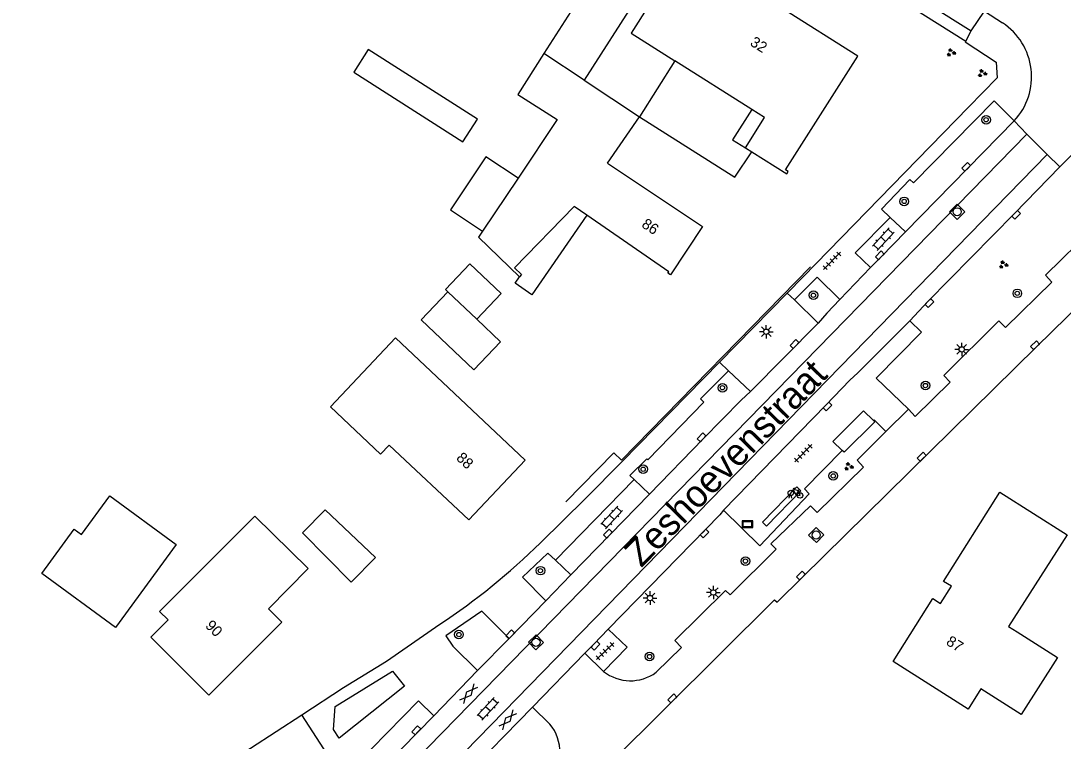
# Model space of a CAD drawing. Extents: x 136000 to 141000, y 400494 to 402006.
# Drawn here: x 137911.7 to 138008.3, y 401818.6 to 401885.4 of the extents above; entities that cross this region are included whole.
import ezdxf

# ---------------------------------------------------------------- set-up
doc = ezdxf.new("R2010")
doc.units = 0
for name, color, linetype in [('gg-afsc-erfafscheiding', 7, 'Continuous'), ('gg-afsc-haag', 7, 'Continuous'), ('gg-afsc-hekwerk', 7, 'Continuous'), ('gg-afsc-muur', 7, 'Continuous'), ('gg-anno-huisnummerreeks BGT', 7, 'Continuous'), ('gg-anno-openbare ruimte label', 7, 'Continuous'), ('gg-bbg-abri', 7, 'Continuous'), ('gg-bbg-bijgebouw', 7, 'Continuous'), ('gg-bbg-gedigitaliseerde bebouwing', 7, 'Continuous'), ('gg-bbg-gedigitaliseerde bijgebouw', 7, 'Continuous'), ('gg-bbg-hoofdgebouw', 7, 'Continuous'), ('gg-bbg-luifel en loopbrug', 7, 'Continuous'), ('gg-bbg-tussenscheiding', 7, 'Continuous'), ('gg-knt-verharding', 7, 'Continuous'), ('gg-knt-verharding nz', 7, 'Continuous'), ('gt-grn-weggrens', 7, 'Continuous'), ('gt-symb-boom', 7, 'Continuous'), ('gt-symb-fietsenrek', 7, 'Continuous'), ('gt-symb-gesloten verharding', 7, 'Continuous'), ('gt-symb-groenvak', 7, 'Continuous'), ('gt-symb-informatiebord', 7, 'Continuous'), ('gt-symb-klinker verharding', 7, 'Continuous'), ('gt-symb-kolk', 7, 'Continuous'), ('gt-symb-lichtmast', 7, 'Continuous'), ('gt-symb-rioolschacht', 7, 'Continuous'), ('gt-symb-tegel verharding', 7, 'Continuous')]:
    doc.layers.add(name, color=color, linetype=linetype)

# ---------------------------------------------------------------- blocks, each defined once
blk = doc.blocks.new('gt0-BOOM')
at = {"layer": 'gt-symb-boom'}
for radius in [0.4, 0.2]:
    blk.add_circle((0, 0), radius, dxfattribs=at)
blk = doc.blocks.new('gt0-GRVAK')
at = {"layer": 'gt-symb-groenvak'}
for p, q in [((-0.11, 0.189), (-0.228, 0.24)), ((-0.182, 0.153), (0.088, 0.153)), ((-0.091, 0.211), (-0.156, 0.322)), ((-0.047, 0.214), (-0.047, 0.393)), ((-0.004, 0.211), (0.061, 0.322)), ((0.015, 0.189), (0.133, 0.24)), ((0.262, -0.052), (0.197, 0.059)), ((0.305, -0.049), (0.305, 0.13)), ((0.349, -0.052), (0.414, 0.059)), ((-0.245, -0.228), (-0.363, -0.177)), ((-0.318, -0.264), (-0.047, -0.264)), ((-0.226, -0.206), (-0.291, -0.095)), ((-0.183, -0.203), (-0.183, -0.024)), ((-0.139, -0.206), (-0.074, -0.095)), ((-0.12, -0.228), (-0.002, -0.177)), ((0.243, -0.074), (0.125, -0.023)), ((0.17, -0.11), (0.441, -0.11)), ((0.368, -0.074), (0.486, -0.023))]:
    blk.add_line(p, q, dxfattribs=at)
blk = doc.blocks.new('gt0-TEG1')
at = {"layer": 'gt-symb-tegel verharding'}
for p, q in [((-1.125, 0), (1.125, 0)), ((-0.9, -0.25), (-0.9, 0.25)), ((-0.45, -0.25), (-0.45, 0.25)), ((0, -0.25), (0, 0.25)), ((0.45, -0.25), (0.45, 0.25)), ((0.9, -0.25), (0.9, 0.25))]:
    blk.add_line(p, q, dxfattribs=at)
blk = doc.blocks.new('gt0-KOLK')
at = {"layer": 'gt-symb-kolk'}
blk.add_lwpolyline([(0, 0), (0.375, 0), (0.375, 0.4), (-0.375, 0.4), (-0.375, 0), (0, 0)], dxfattribs=at)
blk = doc.blocks.new('gt0-KL1')
at = {"layer": 'gt-symb-klinker verharding'}
for p, q in [((-1.15, 0.3), (1.15, 0.3)), ((-1, -0.3), (-1, 0.3)), ((-0.5, 0.3), (-0.5, 0.45)), ((0, -0.3), (0, 0.3)), ((0.5, 0.3), (0.5, 0.45)), ((1, -0.3), (1, 0.3)), ((-1.15, -0.3), (1.15, -0.3)), ((-0.5, -0.45), (-0.5, -0.3)), ((0.5, -0.45), (0.5, -0.3))]:
    blk.add_line(p, q, dxfattribs=at)
blk = doc.blocks.new('gt0-LMAST')
at = {"layer": 'gt-symb-lichtmast'}
for p, q in [((-0.182, 0.173), (-0.447, 0.438)), ((-0.005, 0.246), (-0.005, 0.621)), ((0.172, 0.173), (0.437, 0.438)), ((-0.255, -0.004), (-0.63, -0.004)), ((-0.182, -0.181), (-0.447, -0.446)), ((-0.005, -0.254), (-0.005, -0.629)), ((0.437, -0.446), (0.172, -0.181)), ((0.245, -0.004), (0.62, -0.004))]:
    blk.add_line(p, q, dxfattribs=at)
blk.add_circle((-0.005, -0.004), 0.25, dxfattribs=at)
blk = doc.blocks.new('gt0-RS')
at = {"layer": 'gt-symb-rioolschacht'}
blk.add_lwpolyline([(-0.5, -0.5), (0.5, -0.5), (0.5, 0.5), (-0.5, 0.5)], close=True, dxfattribs=at)
blk.add_circle((0, 0), 0.375, dxfattribs=at)
blk = doc.blocks.new('gt0-IBORD')
at = {"layer": 'gt-symb-informatiebord'}
blk.add_lwpolyline([(-0.5, 0.295), (-0.5, -0.295), (0.5, -0.295), (0.5, 0.295), (-0.5, 0.295)], dxfattribs=at)
blk.add_lwpolyline([(-0.417, -0.212), (0.417, -0.212), (0.417, 0.212), (-0.417, 0.212)], close=True, dxfattribs=at)
blk = doc.blocks.new('gt0-FREK')
at = {"layer": 'gt-symb-fietsenrek'}
for p, q in [((0.259, 0.762), (0.294, 0.823)), ((0.54, 0.335), (0.259, 0.762)), ((0.294, 0.823), (0.767, 0.714)), ((0.767, 0.714), (0.54, 0.335)), ((0.757, 0.841), (0.866, 0.816)), ((0.767, 0.714), (0.84, 0.822)), ((0.895, 0.252), (0.767, 0.714))]:
    blk.add_line(p, q, dxfattribs=at)
for points in [[(-0.124, 0), (-0.047, 0.312), (0.053, 0.312), (0.12, 0)], [(0.036, 0.476), (0.228, 0.708), (0.259, 0.762)], [(0.294, 0.823), (0.36, 0.937), (0.452, 0.935)], [(0.54, 0.335), (0.555, 0.305), (0.895, 0.252)]]:
    blk.add_lwpolyline(points, dxfattribs=at)
for centre in [(0.036, 0.476), (0.895, 0.252)]:
    blk.add_circle(centre, 0.252, dxfattribs=at)
blk = doc.blocks.new('gt0-GESVH1')
at = {"layer": 'gt-symb-gesloten verharding'}
for p, q in [((-0.992, -0.261), (0.008, 0.239)), ((0.008, -0.261), (-0.992, 0.239)), ((0.008, 0.239), (1.008, -0.261)), ((1.008, 0.239), (0.008, -0.261))]:
    blk.add_line(p, q, dxfattribs=at)

msp = doc.modelspace()

# ---------------------------------------------------------------- linework, layer by layer
at = {"layer": 'gg-afsc-erfafscheiding'}
msp.add_line((137966.665, 401845.333), (137962.24, 401840.784), dxfattribs=at)
at = {"layer": 'gg-afsc-haag'}
msp.add_line((137916.005, 401806.962), (137937.768, 401821.037), dxfattribs=at)
at = {"layer": 'gg-afsc-hekwerk'}
msp.add_lwpolyline([(137984.892, 401862.572), (137967.38, 401844.635), (137966.665, 401845.333)], dxfattribs=at)
at = {"layer": 'gg-afsc-muur'}
msp.add_lwpolyline([(137969.048, 401876.493), (137977.887, 401870.892), (137979.45, 401873.22)], dxfattribs=at)
at = {"layer": 'gg-bbg-abri'}
for points in [[(137990.721, 401848.334), (137989.795, 401849.216), (137986.958, 401846.389), (137987.834, 401845.555)], [(137990.721, 401848.334), (137990.855, 401848.206), (137988.018, 401845.379), (137987.834, 401845.555)]]:
    msp.add_lwpolyline(points, dxfattribs=at)
at = {"layer": 'gg-bbg-bijgebouw'}
msp.add_line((137942.35, 401833.35), (137944.6, 401835.64), dxfattribs=at)
at = {"layer": 'gg-bbg-gedigitaliseerde bebouwing'}
for p, q in [((137969.96, 401886.87), (137968.282, 401884.244)), ((137968.282, 401884.244), (137972.322, 401881.679)), ((137963.923, 401879.878), (137960.191, 401882.343)), ((137979.46, 401877.172), (137972.322, 401881.679)), ((137963.923, 401879.878), (137969.048, 401876.493)), ((137957.799, 401870.791), (137954.52, 401865.877))]:
    msp.add_line(p, q, dxfattribs=at)
for points in [[(137960.191, 401882.343), (137957.767, 401878.552), (137961.424, 401876.221), (137957.799, 401870.791)], [(137978.861, 401873.592), (137980.647, 401876.422), (137979.46, 401877.172)], [(137954.52, 401865.877), (137954.15, 401865.324), (137957.93, 401861.66)], [(137958.47, 401844.66), (137946.444, 401855.982), (137940.412, 401849.581)], [(138002.431, 401841.67), (138008.667, 401837.735), (138003.255, 401829.217), (138004.036, 401828.72)], [(137938.34, 401834.61), (137933.399, 401839.446), (137924.592, 401830.612), (137925.374, 401829.832), (137923.78, 401828.234), (137929.16, 401822.87)], [(138004.036, 401828.72), (138007.775, 401826.345), (138004.424, 401821.07), (138000.685, 401823.445)], [(138000.685, 401823.445), (137999.495, 401821.572), (137992.54, 401825.978)]]:
    msp.add_lwpolyline(points, dxfattribs=at)
at = {"layer": 'gg-bbg-gedigitaliseerde bijgebouw'}
for p, q in [((137965.08, 401889.99), (137960.191, 401882.343)), ((137968.848, 401887.581), (137963.923, 401879.878)), ((137953.967, 401857.71), (137956.167, 401855.619))]:
    msp.add_line(p, q, dxfattribs=at)
for points in [[(137951.286, 401860.26), (137951.069, 401860.467), (137953.343, 401862.858), (137956.241, 401860.102), (137953.967, 401857.71)], [(137956.167, 401855.619), (137953.692, 401853.015), (137948.811, 401857.657), (137951.286, 401860.26)], [(137926.129, 401836.838), (137920.498, 401829.133), (137913.664, 401834.127), (137916.676, 401838.248), (137917.36, 401837.748), (137919.98, 401841.332), (137926.129, 401836.838)], [(137942.35, 401833.35), (137937.824, 401837.911), (137939.935, 401840.053), (137944.6, 401835.64)]]:
    msp.add_lwpolyline(points, dxfattribs=at)
at = {"layer": 'gg-bbg-hoofdgebouw'}
for p, q in [((137966.073, 401872.186), (137969.048, 401876.493)), ((137978.861, 401873.592), (137979.45, 401873.22)), ((137979.45, 401873.22), (137982.69, 401871.2))]:
    msp.add_line(p, q, dxfattribs=at)
for points in [[(137982.69, 401871.2), (137982.83, 401871.42), (137982.57, 401871.58), (137989.27, 401882.11), (137975.39, 401890.92), (137975.23, 401890.65)], [(137966.073, 401872.186), (137974.9, 401866.3), (137971.91, 401861.82), (137971.69, 401861.99), (137971.77, 401862.1), (137964.175, 401867.351)], [(137964.175, 401867.351), (137962.99, 401868.17), (137957.48, 401862.47), (137958.12, 401861.85), (137957.93, 401861.66)], [(137940.412, 401849.581), (137945.07, 401845.2), (137945.87, 401846.05), (137953.25, 401839.12), (137958.47, 401844.66)], [(137996.95, 401831.369), (137997.96, 401832.96), (137997.23, 401833.4), (138002.431, 401841.67)], [(137938.34, 401834.61), (137934.68, 401830.85), (137935.9, 401829.63), (137929.16, 401822.87)], [(137992.54, 401825.978), (137996.24, 401831.82), (137996.95, 401831.369)]]:
    msp.add_lwpolyline(points, dxfattribs=at)
at = {"layer": 'gg-bbg-luifel en loopbrug'}
msp.add_line((137972.322, 401881.679), (137969.048, 401876.493), dxfattribs=at)
for points in [[(137942.573, 401880.627), (137952.683, 401874.164), (137954.03, 401876.271), (137943.919, 401882.734), (137942.573, 401880.627)], [(137979.46, 401877.172), (137977.673, 401874.342), (137978.861, 401873.592)], [(137957.799, 401870.791), (137954.819, 401872.78), (137951.539, 401867.865), (137954.52, 401865.877)], [(137964.175, 401867.351), (137959.083, 401859.986), (137957.52, 401861.067), (137957.93, 401861.66)]]:
    msp.add_lwpolyline(points, dxfattribs=at)
at = {"layer": 'gg-bbg-tussenscheiding'}
msp.add_line((137951.286, 401860.26), (137953.967, 401857.71), dxfattribs=at)
at = {"layer": 'gg-knt-verharding'}
for p, q in [((137999.783, 401884.462), (138001.016, 401886.274)), ((138001.016, 401886.274), (138002.691, 401885.196)), ((137993.703, 401865.811), (138003.775, 401876.119)), ((138003.775, 401876.119), (138004.946, 401874.871)), ((138004.946, 401874.871), (138006.822, 401873.001)), ((138008.003, 401871.833), (138010.68, 401874.563)), ((138006.822, 401873.001), (137934.076, 401798.339)), ((138006.822, 401873.001), (138008.003, 401871.833)), ((137993.703, 401865.811), (137992.291, 401867.156)), ((137990.467, 401862.498), (137987.619, 401859.546)), ((137976.468, 401853.726), (137982.747, 401860.138)), ((137985.617, 401857.363), (137983.42, 401859.501)), ((137979.344, 401851.006), (137985.617, 401857.363)), ((137977.295, 401852.944), (137979.344, 401851.006)), ((137991.861, 401847.318), (137993.98, 401849.373)), ((137961.258, 401835.373), (137968.562, 401842.868)), ((137969.975, 401841.49), (137968.562, 401842.868)), ((137962.685, 401834.01), (137969.975, 401841.49)), ((137962.685, 401834.01), (137961.258, 401835.373)), ((137960.381, 401831.615), (137962.685, 401834.01)), ((137956.985, 401828.13), (137960.381, 401831.615)), ((137954.059, 401825.141), (137956.985, 401828.13)), ((137959.138, 401821.751), (137963.991, 401826.745)), ((137963.991, 401826.745), (137965.72, 401825.067)), ((137949.996, 401820.95), (137954.059, 401825.141)), ((137948.592, 401822.35), (137939.895, 401813.463)), ((137949.996, 401820.95), (137948.592, 401822.35)), ((137940.145, 401817.354), (137937.768, 401821.037)), ((137960.747, 401820.185), (137959.138, 401821.751)), ((137941.293, 401812.071), (137949.996, 401820.95))]:
    msp.add_line(p, q, dxfattribs=at)
for points in [[(137880.886, 401957.924), (137937.788, 401922.146), (137999.278, 401883.51)], [(137989.798, 401893.33), (137988.63, 401891.471), (137999.783, 401884.462)], [(137999.278, 401883.51), (137999.225, 401883.426), (138002.104, 401881.541), (138002.204, 401880.088)], [(137982.747, 401860.138), (137984.229, 401861.651), (137999.534, 401877.377), (138002.204, 401880.088)], [(138003.775, 401876.119), (138001.905, 401877.968), (137994.428, 401870.364), (137994.114, 401870.661), (137991.46, 401867.921), (137992.291, 401867.156)], [(138004.946, 401874.871), (137943.022, 401811.44), (137931.758, 401800.418), (137930.613, 401801.602)], [(137994.085, 401857.576), (137995.78, 401859.347), (138003.81, 401867.529), (138008.003, 401871.833)], [(137993.98, 401849.373), (137994.602, 401848.707), (137997.831, 401851.865), (137997.236, 401852.507), (138002.36, 401857.569), (138002.966, 401856.941), (138007.261, 401861.154), (138006.667, 401861.81), (138011.086, 401866.119), (138011.726, 401865.513), (138015.663, 401869.388), (138015.084, 401869.969), (138015.852, 401870.833)], [(137932.851, 401783.862), (137933.76, 401784.767), (137934.015, 401784.527), (137961.351, 401811.623), (137981.568, 401831.695), (137981.799, 401831.48), (137984.14, 401833.81), (138005.833, 401855.156), (138020.002, 401869.043)], [(137992.291, 401867.156), (137989.034, 401863.876), (137990.467, 401862.498)], [(137990.467, 401862.498), (137991.455, 401863.495), (137993.703, 401865.811)], [(137983.42, 401859.501), (137985.521, 401861.612), (137987.619, 401859.546)], [(137987.619, 401859.546), (137986.408, 401858.291), (137985.617, 401857.363)], [(137976.842, 401840.025), (137986.329, 401849.759), (137988.555, 401852.065), (137989.291, 401852.732), (137994.085, 401857.576)], [(137993.98, 401849.373), (137990.977, 401852.249), (137995.168, 401856.509), (137994.085, 401857.576)], [(137959.866, 401836.993), (137964.058, 401841.093), (137967.461, 401844.528), (137976.468, 401853.726)], [(137968.562, 401842.868), (137968.171, 401843.234), (137969.718, 401844.773), (137969.834, 401844.69), (137975.016, 401850.014), (137974.694, 401850.328), (137977.295, 401852.944)], [(137969.975, 401841.49), (137974.952, 401846.62), (137978.485, 401850.211), (137979.344, 401851.006)], [(137991.861, 401847.318), (137990.781, 401848.399), (137990.721, 401848.334)], [(137970.582, 401824.98), (137972.951, 401827.279), (137972.316, 401827.938), (137977.01, 401832.577), (137977.454, 401832.177), (137981.701, 401836.383), (137981.215, 401836.893), (137984.897, 401840.417), (137985.524, 401839.797), (137989.8, 401844.009), (137989.227, 401844.658), (137991.861, 401847.318)], [(137987.834, 401845.555), (137984.348, 401841.989), (137984.786, 401841.529), (137980.208, 401836.692), (137976.842, 401840.025)], [(137976.842, 401840.025), (137976.491, 401839.573), (137966.137, 401828.969)], [(137961.258, 401835.373), (137960.575, 401836.017), (137958.216, 401833.788), (137960.381, 401831.615)], [(137956.985, 401828.13), (137954.449, 401830.653), (137951.115, 401828.353), (137951.744, 401827.402), (137954.059, 401825.141)], [(137937.768, 401821.037), (137941.643, 401823.562), (137945.627, 401826.006), (137950.54, 401829.437)], [(137966.137, 401828.969), (137964.834, 401827.596), (137963.991, 401826.745)], [(137965.72, 401825.067), (137967.911, 401827.312), (137966.137, 401828.969)], [(137947.285, 401823.701), (137941.221, 401818.875), (137940.705, 401819.664), (137940.869, 401821.819), (137946.168, 401825.092), (137947.285, 401823.701)], [(137959.138, 401821.751), (137952.683, 401815.148), (137936.839, 401798.865), (137934.749, 401796.556)]]:
    msp.add_lwpolyline(points, dxfattribs=at)
for centre, radius, start, end in [((137999.393, 401880.199), 5.987, 317.04523, 56.5751), ((137917.29, 401880.01), 60.524, 303.32404, 314.7053), ((137968.208, 401828.19), 3.993, 231.46104, 306.48869), ((137957.805, 401817.691), 3.857, 314.4033, 40.29653)]:
    msp.add_arc(centre, radius, start, end, dxfattribs=at)
at = {"layer": 'gg-knt-verharding nz'}
msp.add_lwpolyline([(137980.805, 401838.529), (137980.439, 401838.886), (137983.627, 401842.168), (137983.993, 401841.81), (137980.805, 401838.529)], dxfattribs=at)
at = {"layer": 'gt-grn-weggrens'}
for p, q in [((137999.278, 401883.51), (137999.783, 401884.462)), ((137983.42, 401859.501), (137982.747, 401860.138)), ((137977.295, 401852.944), (137976.468, 401853.726))]:
    msp.add_line(p, q, dxfattribs=at)

# ---------------------------------------------------------------- block references
at = {"layer": 'gt-symb-boom'}
for p in [(138001.165, 401876.207), (137993.575, 401868.641), (137985.17, 401859.938), (138004.058, 401860.116), (137995.545, 401851.57), (137976.736, 401851.362), (137969.393, 401843.81), (137987.004, 401843.193), (137978.868, 401835.289), (137959.87, 401834.405), (137952.327, 401828.476), (137969.988, 401826.444)]:
    msp.add_blockref('gt0-BOOM', p, dxfattribs=at)
at = {"layer": 'gt-symb-fietsenrek'}
msp.add_blockref('gt0-FREK', (137983.031, 401841.128), dxfattribs=at)
at = {"layer": 'gt-symb-gesloten verharding'}
for p, rotation in [((137953.216, 401823.002), 49.175064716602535), ((137956.837, 401820.582), 49.17506472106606)]:
    msp.add_blockref('gt0-GESVH1', p, dxfattribs=dict(at, rotation=rotation))
at = {"layer": 'gt-symb-groenvak'}
for p in [(137997.906, 401882.436), (138000.797, 401880.514), (138002.755, 401862.768), (137988.426, 401844.055)]:
    msp.add_blockref('gt0-GRVAK', p, dxfattribs=at)
at = {"layer": 'gt-symb-informatiebord'}
msp.add_blockref('gt0-IBORD', (137979.05, 401838.714), dxfattribs=at)
at = {"layer": 'gt-symb-klinker verharding', "rotation": -132.89389072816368}
for p in [(137991.633, 401865.141), (137966.478, 401839.338), (137955.015, 401821.599)]:
    msp.add_blockref('gt0-KL1', p, dxfattribs=at)
at = {"layer": 'gt-symb-kolk'}
for p, rotation in [((137999.468, 401871.702), 45.616305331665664), ((138003.81, 401867.529), -134.46358108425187), ((137991.455, 401863.495), 45.27960072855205), ((137995.78, 401859.347), -133.75029526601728), ((137983.566, 401855.277), 45.330987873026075), ((138005.833, 401855.156), 44.429343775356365), ((137986.329, 401849.759), -134.2695754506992), ((137974.952, 401846.62), 45.86735988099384), ((137995.335, 401844.827), 44.53205682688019), ((137966.274, 401837.701), 45.81030460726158), ((137974.94, 401837.984), -134.31522249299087), ((137984.14, 401833.81), 44.537809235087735), ((137957.214, 401828.36), 45.097005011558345), ((137964.834, 401827.596), -133.49901935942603), ((137972.236, 401822.423), 44.811696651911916), ((137948.523, 401819.457), 45.61053842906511)]:
    msp.add_blockref('gt0-KOLK', p, dxfattribs=dict(at, rotation=rotation))
at = {"layer": 'gt-symb-lichtmast'}
for p in [(137980.802, 401856.558), (137998.913, 401854.921), (137975.901, 401832.384), (137970.033, 401831.868)]:
    msp.add_blockref('gt0-LMAST', p, dxfattribs=at)
at = {"layer": 'gt-symb-rioolschacht'}
for p, rotation in [((137998.487, 401867.681), 134.66901212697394), ((137985.428, 401837.707), -133.27086277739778), ((137959.462, 401827.761), 43.26498677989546)]:
    msp.add_blockref('gt0-RS', p, dxfattribs=dict(at, rotation=rotation))
at = {"layer": 'gt-symb-tegel verharding'}
for p, rotation in [((137986.883, 401863.127), 45.32415936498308), ((137984.235, 401845.29), 45.44539991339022), ((137965.866, 401826.941), 44.02760489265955)]:
    msp.add_blockref('gt0-TEG1', p, dxfattribs=dict(at, rotation=rotation))

# ---------------------------------------------------------------- texts
at = {"layer": 'gg-anno-huisnummerreeks BGT'}
for s, rotation, p in [('32', 327.6, (137979.22, 401883.159)), ('86', 326.3, (137969.167, 401866.314)), ('88', 316.7, (137952.003, 401844.763)), ('90', 315.1, (137928.756, 401829.23)), ('87', 327.7, (137997.382, 401827.599))]:
    msp.add_text(s, height=1, rotation=rotation, dxfattribs=at).set_placement(p)
at = {"layer": 'gg-anno-openbare ruimte label'}
msp.add_text('Zeshoevenstraat', height=2.5, rotation=45.7, dxfattribs=at).set_placement((137969.212, 401834.617))

doc.saveas('drawing.dxf')
